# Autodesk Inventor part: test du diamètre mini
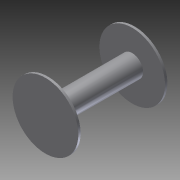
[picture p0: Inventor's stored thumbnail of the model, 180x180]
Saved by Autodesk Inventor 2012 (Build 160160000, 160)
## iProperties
Created: 2013-09
Part Number: test du diamètre mini
Material: Default
Document SubType Name: Modeling
Designer: hilarion
Density: 1 g/cm^3
Author: hilarion
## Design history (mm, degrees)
sketch "Esquisse1"
  geometry: L1 (0, 0)-(-70, 0); L2 (-70, 0)-(-70, 5); L3 (-70, 5)-(-23.333, 5); L4 (0, 5)-(0, 0); L5 (0, 190)-(-70, 190); L6 (-70, 190)-(-70, 185); L7 (-70, 185)-(-23.333, 185); L8 (0, 185)-(0, 190); L9 (-23.333, 185)-(-23.333, 5); L10 (0, 5)-(0, 185)
  constraints: 20 end point, 5 parallel, 2 horizontal, 2 perpendicular
  dimensions: "d5" = 190 distance between parallel lines of L1 L5; "d7" = 70 distance between parallel lines of L6 L8; "d8" = 70 distance between parallel lines of L10 L2 (= d7); "d9" = 23.33333 distance between parallel lines of L10 L9 (= 0.333333 x d7)
revolve "Révolution1" sketch "Esquisse1" stored, may be unused: angle "d6" = 90 deg
node "Solide1"
other parameters: "sa_0" = 159000
